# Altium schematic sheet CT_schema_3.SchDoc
size 295 x 165 mm
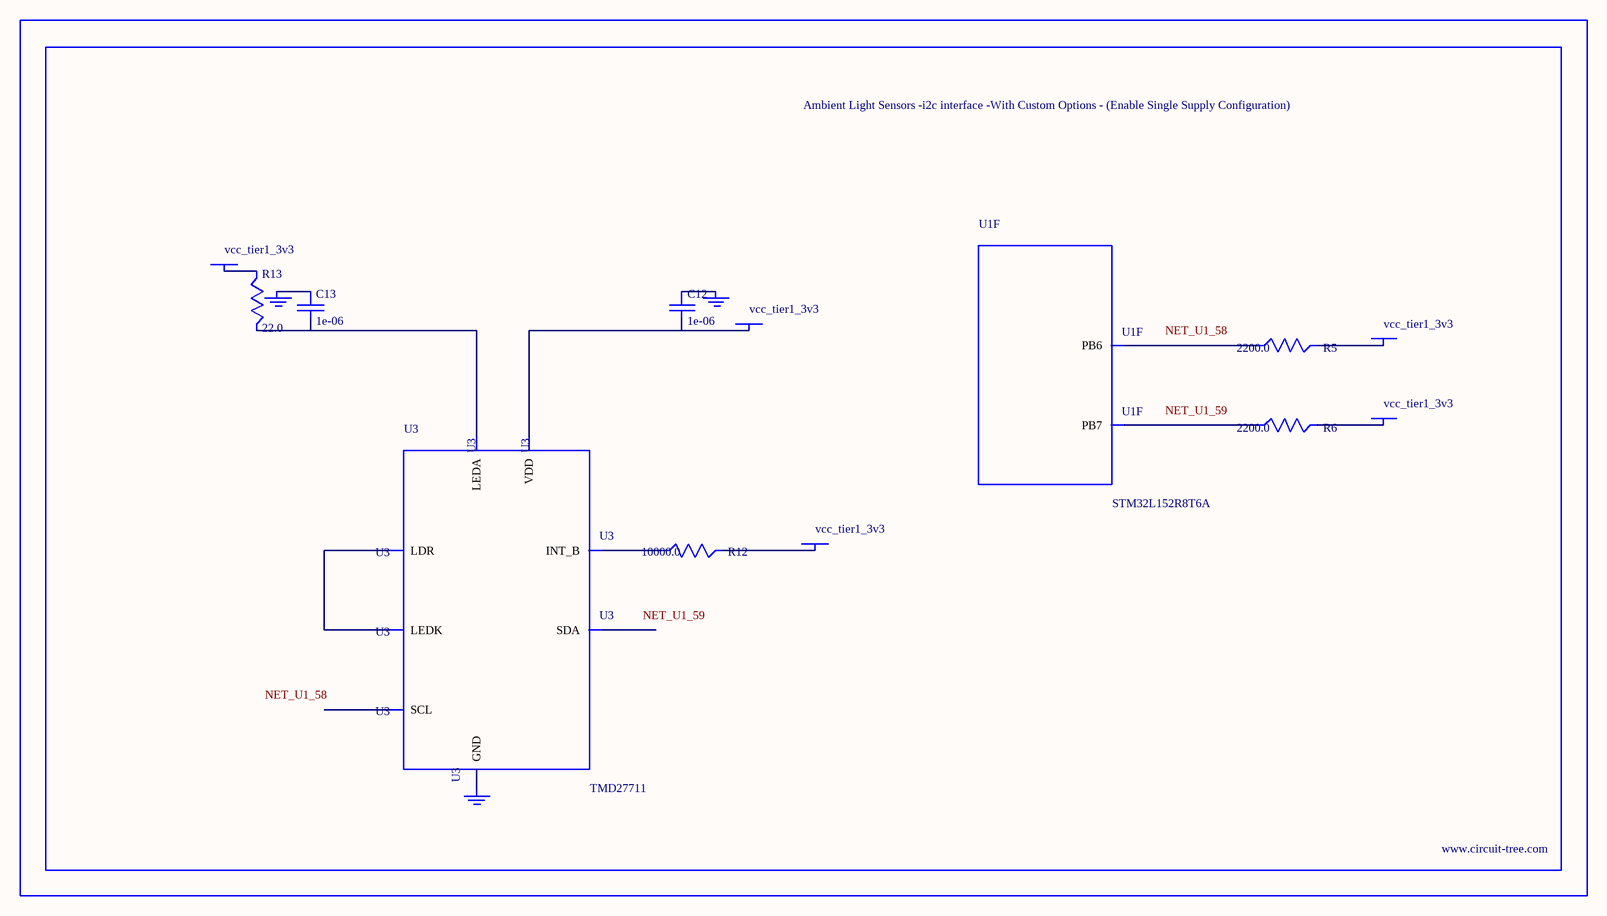
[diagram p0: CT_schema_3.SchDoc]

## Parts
BORDER2  (no value)
C12  1e-06  [C0603]
C13  1e-06  [C0603]
GND_INSTANCE_2_0  (no value)
GND_INSTANCE_2_1  (no value)
GND_INSTANCE_2_2  (no value)
POWER_INSTANCE_2_0  vcc_tier1_3v3
POWER_INSTANCE_2_1  vcc_tier1_3v3
POWER_INSTANCE_2_2  vcc_tier1_3v3
POWER_INSTANCE_2_3  vcc_tier1_3v3
POWER_INSTANCE_2_4  vcc_tier1_3v3
R5  2200.0  [R0603]
R6  2200.0  [R0603]
R12  10000.0  [R0603]
R13  22.0  [R0603]
U1  STM32L152R8T6A  [LQFP64]  (part F of 6)
U3  TMD27711  [SMD-8]

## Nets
NetC12_1: C12.1 GND_INSTANCE_2_0.0(GND)
NetC12_2: C12.2 POWER_INSTANCE_2_0.0(PWR) U3.1(VDD)
NetC13_1: C13.1 GND_INSTANCE_2_1.0(GND)
NetC13_2: C13.2 R13.2 U3.4(LEDA)
NetGND_INSTANCE_2_2_0: GND_INSTANCE_2_2.0(GND) U3.3(GND)
NetPOWER_INSTANCE_2_1_0: POWER_INSTANCE_2_1.0(PWR) R13.1
NetPOWER_INSTANCE_2_2_0: POWER_INSTANCE_2_2.0(PWR) R12.2
NetPOWER_INSTANCE_2_3_0: POWER_INSTANCE_2_3.0(PWR) R5.2
NetPOWER_INSTANCE_2_4_0: POWER_INSTANCE_2_4.0(PWR) R6.2
NetR5_1: R5.1 U1.58(PB6)
NetR6_1: R6.1 U1.59(PB7)
NetR12_1: R12.1 U3.7(INT_B)
NetU3_5: U3.5(LEDK) U3.6(LDR)

Not connected (* = marked no-connect by the designer): U3 2(SCL) 8(SDA)

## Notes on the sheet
- Labels drawn without touching a wire or pin: NET_U1_58, NET_U1_59

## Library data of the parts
BORDER2 = BORDER_PAGE2
C12 C13 = C0603C105K3RACTU
GND_INSTANCE_2_0-GND_INSTANCE_2_2 = GND
POWER_INSTANCE_2_0-POWER_INSTANCE_2_4 = PWR
R5 R6 = RC0603JR-072K2L
R12 = RC0603JR-0710KL
R13 = RC0603JR-0722RL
